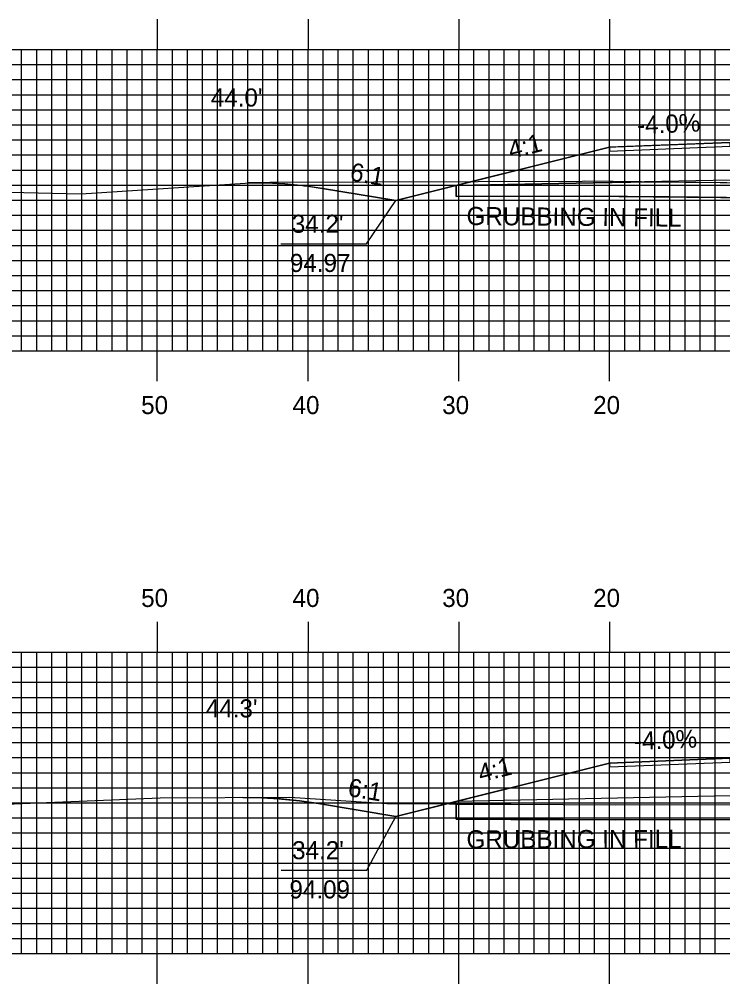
# Model space of a CAD drawing. Extents: x 1778319 to 1778662, y 442591 to 442811.
# Drawn here: x 1778425.2 to 1778471.8, y 442686.7 to 442750.7 of the extents above; entities that cross this region are included whole.
import ezdxf

# ---------------------------------------------------------------- set-up
doc = ezdxf.new("R2010")
doc.units = 0
for name, color, linetype in [('ANNOTATION', 7, 'Continuous'), ('D_Roadway_Centerline', 7, 'Continuous'), ('D_Roadway_Edge_Shoulder', 7, 'Continuous'), ('D_Roadway_SlopeLines', 7, 'Continuous'), ('D_Roadway_SubGrade', 7, 'Continuous'), ('D_Text_Standard', 7, 'Continuous'), ('GRUBBING IN FILL', 7, 'Continuous'), ('H_V ANNOTATION', 7, 'Continuous'), ('MAJOR', 7, 'Continuous'), ('MINOR', 7, 'Continuous'), ('S_Roadway_Centerline', 7, 'Continuous')]:
    doc.layers.add(name, color=color, linetype=linetype)

msp = doc.modelspace()

# ---------------------------------------------------------------- linework, layer by layer
at = {"layer": 'ANNOTATION'}
for points in [[(1778442.49, 442735.773), (1778448.181, 442735.773), (1778450.129, 442738.634)], [(1778442.51, 442694.195), (1778448.202, 442694.195), (1778450.129, 442697.759)]]:
    msp.add_lwpolyline(points, dxfattribs=at)
at = {"layer": 'D_Roadway_Centerline'}
for points in [[(1778440.264, 442739.81), (1778441.026, 442739.808), (1778441.513, 442739.806), (1778442.763, 442739.744), (1778443.934, 442739.632), (1778444.014, 442739.624), (1778444.132, 442739.607), (1778445.264, 442739.445), (1778450.129, 442738.634), (1778453.923, 442739.583), (1778454.129, 442739.634), (1778464.303, 442742.177), (1778464.723, 442742.194), (1778472.303, 442742.497)], [(1778439.985, 442699.025), (1778441.235, 442699.002), (1778442.382, 442698.933), (1778442.485, 442698.927), (1778442.554, 442698.92), (1778443.735, 442698.798), (1778444.985, 442698.616), (1778450.129, 442697.759), (1778454.13, 442698.759), (1778464.303, 442701.302), (1778472.303, 442701.622)]]:
    msp.add_lwpolyline(points, dxfattribs=at)
at = {"layer": 'D_Roadway_Edge_Shoulder'}
for points in [[(1778472.303, 442742.497), (1778464.303, 442742.177), (1778464.303, 442741.927), (1778472.303, 442742.247)], [(1778472.303, 442701.622), (1778464.303, 442701.302), (1778464.303, 442701.052), (1778472.303, 442701.372)]]:
    msp.add_lwpolyline(points, close=True, dxfattribs=at)
at = {"layer": 'D_Roadway_SlopeLines'}
for points in [[(1778464.303, 442742.177), (1778450.129, 442738.634)], [(1778450.129, 442738.634), (1778445.264, 442739.445), (1778444.014, 442739.624), (1778442.763, 442739.744), (1778441.513, 442739.806), (1778440.264, 442739.81)], [(1778464.303, 442701.302), (1778450.129, 442697.759)], [(1778450.129, 442697.759), (1778444.985, 442698.616), (1778443.735, 442698.798), (1778442.485, 442698.927), (1778441.235, 442699.002), (1778439.985, 442699.025)]]:
    msp.add_lwpolyline(points, dxfattribs=at)
at = {"layer": 'D_Roadway_SubGrade'}
for points in [[(1778472.303, 442739.997), (1778454.129, 442739.634), (1778464.303, 442742.177), (1778464.303, 442741.927), (1778472.303, 442742.247), (1778484.303, 442742.487), (1778496.303, 442742.247), (1778504.303, 442741.927), (1778504.303, 442742.177), (1778514.476, 442739.634), (1778496.303, 442739.997), (1778484.303, 442740.237)], [(1778472.303, 442699.122), (1778454.13, 442698.759), (1778464.303, 442701.302), (1778464.303, 442701.052), (1778472.303, 442701.372), (1778484.303, 442701.612), (1778496.303, 442701.372), (1778504.303, 442701.052), (1778504.303, 442701.302), (1778514.477, 442698.759), (1778496.303, 442699.122), (1778484.303, 442699.362)]]:
    msp.add_lwpolyline(points, close=True, dxfattribs=at)
at = {"layer": 'GRUBBING IN FILL'}
for p, q in [((1778454.129, 442739.634), (1778454.129, 442738.902)), ((1778454.129, 442739.634), (1778454.129, 442738.902)), ((1778454.13, 442698.587), (1778454.13, 442697.587)), ((1778454.13, 442698.587), (1778454.13, 442697.587))]:
    msp.add_line(p, q, dxfattribs=at)
for points in [[(1778454.129, 442739.634), (1778463.216, 442739.816), (1778466.971, 442739.891), (1778473.953, 442739.813), (1778479.619, 442739.785), (1778484.303, 442739.762), (1778484.303, 442738.762), (1778479.609, 442738.785), (1778473.945, 442738.813), (1778468.311, 442738.876), (1778462.676, 442738.938), (1778458.316, 442738.917), (1778454.129, 442738.902)], [(1778454.129, 442739.634), (1778463.216, 442739.816), (1778466.971, 442739.891), (1778473.953, 442739.813), (1778479.619, 442739.785), (1778484.303, 442739.762), (1778484.303, 442738.762), (1778479.609, 442738.785), (1778473.945, 442738.813), (1778468.311, 442738.876), (1778462.676, 442738.938), (1778458.316, 442738.917), (1778454.129, 442738.902)], [(1778454.13, 442697.587), (1778454.13, 442698.587), (1778457.766, 442698.568), (1778461.228, 442698.551), (1778464.69, 442698.535), (1778472.756, 442698.546), (1778480.822, 442698.556), (1778484.303, 442698.587), (1778484.282, 442697.586), (1778480.827, 442697.556), (1778472.758, 442697.546), (1778464.689, 442697.535), (1778461.225, 442697.551)], [(1778454.13, 442697.587), (1778454.13, 442698.587), (1778457.766, 442698.568), (1778461.228, 442698.551), (1778464.69, 442698.535), (1778472.756, 442698.546), (1778480.822, 442698.556), (1778484.303, 442698.587), (1778484.282, 442697.586), (1778480.827, 442697.556), (1778472.758, 442697.546), (1778464.689, 442697.535), (1778461.225, 442697.551)]]:
    msp.add_lwpolyline(points, close=True, dxfattribs=at)
for points in [[(1778454.129, 442738.902), (1778462.503, 442738.932), (1778462.676, 442738.938), (1778473.945, 442738.813), (1778485.273, 442738.757), (1778485.52, 442738.752), (1778485.762, 442738.757), (1778489.107, 442738.751), (1778507.798, 442738.768), (1778510.003, 442738.758), (1778514.476, 442738.775)], [(1778454.129, 442738.902), (1778462.503, 442738.932), (1778462.676, 442738.938), (1778473.945, 442738.813), (1778485.273, 442738.757), (1778485.52, 442738.752), (1778485.762, 442738.757), (1778489.107, 442738.751), (1778507.798, 442738.768), (1778510.003, 442738.758), (1778514.476, 442738.775)], [(1778454.13, 442697.587), (1778457.761, 442697.568), (1778464.689, 442697.535), (1778480.827, 442697.556), (1778487.737, 442697.617), (1778505.516, 442697.916), (1778508.127, 442697.951), (1778512.922, 442697.953), (1778514.477, 442697.957)], [(1778454.13, 442697.587), (1778457.761, 442697.568), (1778464.689, 442697.535), (1778480.827, 442697.556), (1778487.737, 442697.617), (1778505.516, 442697.916), (1778508.127, 442697.951), (1778512.922, 442697.953), (1778514.477, 442697.957)]]:
    msp.add_lwpolyline(points, dxfattribs=at)
at = {"layer": 'MAJOR'}
for p, q in [((1778434.303, 442750.669), (1778434.303, 442748.665)), ((1778444.303, 442750.669), (1778444.303, 442748.665)), ((1778454.303, 442750.669), (1778454.303, 442748.665)), ((1778464.303, 442750.669), (1778464.303, 442748.665)), ((1778344.303, 442748.665), (1778624.303, 442748.665)), ((1778344.303, 442748.665), (1778624.303, 442748.665)), ((1778434.303, 442728.665), (1778434.303, 442748.665)), ((1778444.303, 442728.665), (1778444.303, 442748.665)), ((1778454.303, 442728.665), (1778454.303, 442748.665)), ((1778464.303, 442728.665), (1778464.303, 442748.665)), ((1778344.303, 442743.665), (1778624.303, 442743.665)), ((1778344.303, 442738.665), (1778624.303, 442738.665)), ((1778344.303, 442733.665), (1778624.303, 442733.665)), ((1778344.303, 442728.665), (1778624.303, 442728.665)), ((1778344.303, 442728.665), (1778624.303, 442728.665)), ((1778434.303, 442726.661), (1778434.303, 442728.665)), ((1778444.303, 442726.661), (1778444.303, 442728.665)), ((1778454.303, 442726.661), (1778454.303, 442728.665)), ((1778464.303, 442726.661), (1778464.303, 442728.665)), ((1778434.303, 442710.669), (1778434.303, 442708.665)), ((1778444.303, 442710.669), (1778444.303, 442708.665)), ((1778454.303, 442710.669), (1778454.303, 442708.665)), ((1778464.303, 442710.669), (1778464.303, 442708.665)), ((1778344.303, 442708.665), (1778624.303, 442708.665)), ((1778344.303, 442708.665), (1778624.303, 442708.665)), ((1778434.303, 442688.665), (1778434.303, 442708.665)), ((1778444.303, 442688.665), (1778444.303, 442708.665)), ((1778454.303, 442688.665), (1778454.303, 442708.665)), ((1778464.303, 442688.665), (1778464.303, 442708.665)), ((1778344.303, 442703.665), (1778624.303, 442703.665)), ((1778344.303, 442698.665), (1778624.303, 442698.665)), ((1778344.303, 442693.665), (1778624.303, 442693.665)), ((1778344.303, 442688.665), (1778624.303, 442688.665)), ((1778344.303, 442688.665), (1778624.303, 442688.665)), ((1778434.303, 442686.661), (1778434.303, 442688.665)), ((1778444.303, 442686.661), (1778444.303, 442688.665)), ((1778454.303, 442686.661), (1778454.303, 442688.665)), ((1778464.303, 442686.661), (1778464.303, 442688.665))]:
    msp.add_line(p, q, dxfattribs=at)
at = {"layer": 'MINOR'}
for p, q in [((1778425.303, 442728.665), (1778425.303, 442748.665)), ((1778426.303, 442728.665), (1778426.303, 442748.665)), ((1778427.303, 442728.665), (1778427.303, 442748.665)), ((1778428.303, 442728.665), (1778428.303, 442748.665)), ((1778429.303, 442728.665), (1778429.303, 442748.665)), ((1778430.303, 442728.665), (1778430.303, 442748.665)), ((1778431.303, 442728.665), (1778431.303, 442748.665)), ((1778432.303, 442728.665), (1778432.303, 442748.665)), ((1778433.303, 442728.665), (1778433.303, 442748.665)), ((1778435.303, 442728.665), (1778435.303, 442748.665)), ((1778436.303, 442728.665), (1778436.303, 442748.665)), ((1778437.303, 442728.665), (1778437.303, 442748.665)), ((1778438.303, 442728.665), (1778438.303, 442748.665)), ((1778439.303, 442728.665), (1778439.303, 442748.665)), ((1778440.303, 442728.665), (1778440.303, 442748.665)), ((1778441.303, 442728.665), (1778441.303, 442748.665)), ((1778442.303, 442728.665), (1778442.303, 442748.665)), ((1778443.303, 442728.665), (1778443.303, 442748.665)), ((1778445.303, 442728.665), (1778445.303, 442748.665)), ((1778446.303, 442728.665), (1778446.303, 442748.665)), ((1778447.303, 442728.665), (1778447.303, 442748.665)), ((1778448.303, 442728.665), (1778448.303, 442748.665)), ((1778449.303, 442728.665), (1778449.303, 442748.665)), ((1778450.303, 442728.665), (1778450.303, 442748.665)), ((1778451.303, 442728.665), (1778451.303, 442748.665)), ((1778452.303, 442728.665), (1778452.303, 442748.665)), ((1778453.303, 442728.665), (1778453.303, 442748.665)), ((1778455.303, 442728.665), (1778455.303, 442748.665)), ((1778456.303, 442728.665), (1778456.303, 442748.665)), ((1778457.303, 442728.665), (1778457.303, 442748.665)), ((1778458.303, 442728.665), (1778458.303, 442748.665)), ((1778459.303, 442728.665), (1778459.303, 442748.665)), ((1778460.303, 442728.665), (1778460.303, 442748.665)), ((1778461.303, 442728.665), (1778461.303, 442748.665)), ((1778462.303, 442728.665), (1778462.303, 442748.665)), ((1778463.303, 442728.665), (1778463.303, 442748.665)), ((1778465.303, 442728.665), (1778465.303, 442748.665)), ((1778466.303, 442728.665), (1778466.303, 442748.665)), ((1778467.303, 442728.665), (1778467.303, 442748.665)), ((1778468.303, 442728.665), (1778468.303, 442748.665)), ((1778469.303, 442728.665), (1778469.303, 442748.665)), ((1778470.303, 442728.665), (1778470.303, 442748.665)), ((1778471.303, 442728.665), (1778471.303, 442748.665)), ((1778344.303, 442747.665), (1778624.303, 442747.665)), ((1778344.303, 442746.665), (1778624.303, 442746.665)), ((1778344.303, 442745.665), (1778624.303, 442745.665)), ((1778344.303, 442744.665), (1778624.303, 442744.665)), ((1778344.303, 442742.665), (1778624.303, 442742.665)), ((1778344.303, 442741.665), (1778624.303, 442741.665)), ((1778344.303, 442740.665), (1778624.303, 442740.665)), ((1778344.303, 442739.665), (1778624.303, 442739.665)), ((1778344.303, 442737.665), (1778624.303, 442737.665)), ((1778344.303, 442736.665), (1778624.303, 442736.665)), ((1778344.303, 442735.665), (1778624.303, 442735.665)), ((1778344.303, 442734.665), (1778624.303, 442734.665)), ((1778344.303, 442732.665), (1778624.303, 442732.665)), ((1778344.303, 442731.665), (1778624.303, 442731.665)), ((1778344.303, 442730.665), (1778624.303, 442730.665)), ((1778344.303, 442729.665), (1778624.303, 442729.665)), ((1778425.303, 442688.665), (1778425.303, 442708.665)), ((1778426.303, 442688.665), (1778426.303, 442708.665)), ((1778427.303, 442688.665), (1778427.303, 442708.665)), ((1778428.303, 442688.665), (1778428.303, 442708.665)), ((1778429.303, 442688.665), (1778429.303, 442708.665)), ((1778430.303, 442688.665), (1778430.303, 442708.665)), ((1778431.303, 442688.665), (1778431.303, 442708.665)), ((1778432.303, 442688.665), (1778432.303, 442708.665)), ((1778433.303, 442688.665), (1778433.303, 442708.665)), ((1778435.303, 442688.665), (1778435.303, 442708.665)), ((1778436.303, 442688.665), (1778436.303, 442708.665)), ((1778437.303, 442688.665), (1778437.303, 442708.665)), ((1778438.303, 442688.665), (1778438.303, 442708.665)), ((1778439.303, 442688.665), (1778439.303, 442708.665)), ((1778440.303, 442688.665), (1778440.303, 442708.665)), ((1778441.303, 442688.665), (1778441.303, 442708.665)), ((1778442.303, 442688.665), (1778442.303, 442708.665)), ((1778443.303, 442688.665), (1778443.303, 442708.665)), ((1778445.303, 442688.665), (1778445.303, 442708.665)), ((1778446.303, 442688.665), (1778446.303, 442708.665)), ((1778447.303, 442688.665), (1778447.303, 442708.665)), ((1778448.303, 442688.665), (1778448.303, 442708.665)), ((1778449.303, 442688.665), (1778449.303, 442708.665)), ((1778450.303, 442688.665), (1778450.303, 442708.665)), ((1778451.303, 442688.665), (1778451.303, 442708.665)), ((1778452.303, 442688.665), (1778452.303, 442708.665)), ((1778453.303, 442688.665), (1778453.303, 442708.665)), ((1778455.303, 442688.665), (1778455.303, 442708.665)), ((1778456.303, 442688.665), (1778456.303, 442708.665)), ((1778457.303, 442688.665), (1778457.303, 442708.665)), ((1778458.303, 442688.665), (1778458.303, 442708.665)), ((1778459.303, 442688.665), (1778459.303, 442708.665)), ((1778460.303, 442688.665), (1778460.303, 442708.665)), ((1778461.303, 442688.665), (1778461.303, 442708.665)), ((1778462.303, 442688.665), (1778462.303, 442708.665)), ((1778463.303, 442688.665), (1778463.303, 442708.665)), ((1778465.303, 442688.665), (1778465.303, 442708.665)), ((1778466.303, 442688.665), (1778466.303, 442708.665)), ((1778467.303, 442688.665), (1778467.303, 442708.665)), ((1778468.303, 442688.665), (1778468.303, 442708.665)), ((1778469.303, 442688.665), (1778469.303, 442708.665)), ((1778470.303, 442688.665), (1778470.303, 442708.665)), ((1778471.303, 442688.665), (1778471.303, 442708.665)), ((1778344.303, 442707.665), (1778624.303, 442707.665)), ((1778344.303, 442706.665), (1778624.303, 442706.665)), ((1778344.303, 442705.665), (1778624.303, 442705.665)), ((1778344.303, 442704.665), (1778624.303, 442704.665)), ((1778344.303, 442702.665), (1778624.303, 442702.665)), ((1778344.303, 442701.665), (1778624.303, 442701.665)), ((1778344.303, 442700.665), (1778624.303, 442700.665)), ((1778344.303, 442699.665), (1778624.303, 442699.665)), ((1778344.303, 442697.665), (1778624.303, 442697.665)), ((1778344.303, 442696.665), (1778624.303, 442696.665)), ((1778344.303, 442695.665), (1778624.303, 442695.665)), ((1778344.303, 442694.665), (1778624.303, 442694.665)), ((1778344.303, 442692.665), (1778624.303, 442692.665)), ((1778344.303, 442691.665), (1778624.303, 442691.665)), ((1778344.303, 442690.665), (1778624.303, 442690.665)), ((1778344.303, 442689.665), (1778624.303, 442689.665))]:
    msp.add_line(p, q, dxfattribs=at)
at = {"layer": 'S_Roadway_Centerline'}
for points in [[(1778417.84, 442739.354), (1778429.256, 442739.09), (1778440.814, 442739.846), (1778441.767, 442739.858), (1778462.483, 442739.932), (1778462.664, 442739.938), (1778473.953, 442739.813), (1778485.286, 442739.757), (1778485.518, 442739.752), (1778485.752, 442739.757), (1778489.108, 442739.751), (1778507.8, 442739.768), (1778510.003, 442739.758), (1778520.441, 442739.799), (1778530.487, 442740.045), (1778535.142, 442740.071)], [(1778344.303, 442697.541), (1778351.743, 442697.564), (1778363.809, 442697.941), (1778369.805, 442697.91), (1778375.274, 442698.29), (1778380.708, 442698.555), (1778397.812, 442698.308), (1778404.224, 442698.223), (1778411.588, 442698.3), (1778420.475, 442698.413), (1778434.487, 442699.007), (1778443.083, 442699.035), (1778449.532, 442698.611), (1778457.766, 442698.568), (1778464.69, 442698.535), (1778480.822, 442698.556), (1778487.724, 442698.617), (1778505.501, 442698.916), (1778508.12, 442698.951), (1778512.921, 442698.953), (1778532.182, 442698.997)]]:
    msp.add_lwpolyline(points, dxfattribs=at)

# ---------------------------------------------------------------- texts
at = {"layer": 'ANNOTATION'}
for s, rotation, p in [('-4.0%', 2.29074, (1778466.145, 442743.053)), ('4:1', 14.0329, (1778457.752, 442741.401)), ('6:1', 350.53676, (1778447.029, 442739.978)), ('-4.0%', 2.29053, (1778465.935, 442702.169)), ('4:1', 14.03473, (1778455.752, 442700.026)), ('6:1', 350.54167, (1778446.89, 442699.126))]:
    msp.add_text(s, height=1.2, rotation=rotation, dxfattribs=at).set_placement(p)
for s, p in [("34.2'", (1778443.224, 442736.499)), ('94.97', (1778443.101, 442733.899)), ("34.2'", (1778443.245, 442694.922)), ('94.09', (1778443.068, 442692.322))]:
    msp.add_text(s, height=1.2, dxfattribs=at).set_placement(p)
at = {"layer": 'D_Text_Standard'}
for s, p in [("44.0'", (1778437.852, 442744.878)), ("44.3'", (1778437.521, 442704.334))]:
    msp.add_text(s, height=1.2, dxfattribs=at).set_placement(p)
at = {"layer": 'GRUBBING IN FILL'}
for rotation, p in [(359.54869, (1778454.808, 442737.018)), (0.13842, (1778454.811, 442695.644))]:
    msp.add_text('GRUBBING IN FILL', height=1.2, rotation=rotation, dxfattribs=at).set_placement(p)
at = {"layer": 'H_V ANNOTATION'}
for s, p in [('50', (1778433.232, 442724.465)), ('40', (1778443.275, 442724.465)), ('30', (1778453.2, 442724.465)), ('20', (1778463.211, 442724.465)), ('50', (1778433.232, 442711.665)), ('40', (1778443.275, 442711.665)), ('30', (1778453.2, 442711.665)), ('20', (1778463.211, 442711.665))]:
    msp.add_text(s, height=1.2, dxfattribs=at).set_placement(p)

doc.saveas('drawing.dxf')
